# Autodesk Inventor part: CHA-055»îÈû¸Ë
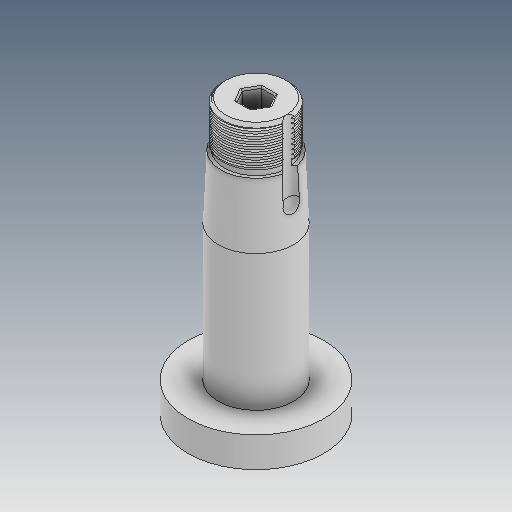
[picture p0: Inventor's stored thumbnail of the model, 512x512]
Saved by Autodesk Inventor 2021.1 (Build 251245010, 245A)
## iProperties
Created: 2019-05
Part Number: CHA-055»îÈû¸Ë
Material: Ogólny
Document SubType Name: Modeling
Designer: user
Density: 1 g/cm^3
Appearance: Domyślna
Author: user
Revision Number: ÈÎºÎ
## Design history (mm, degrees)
feature "ÊäÈë1"
node "Bryła1"
